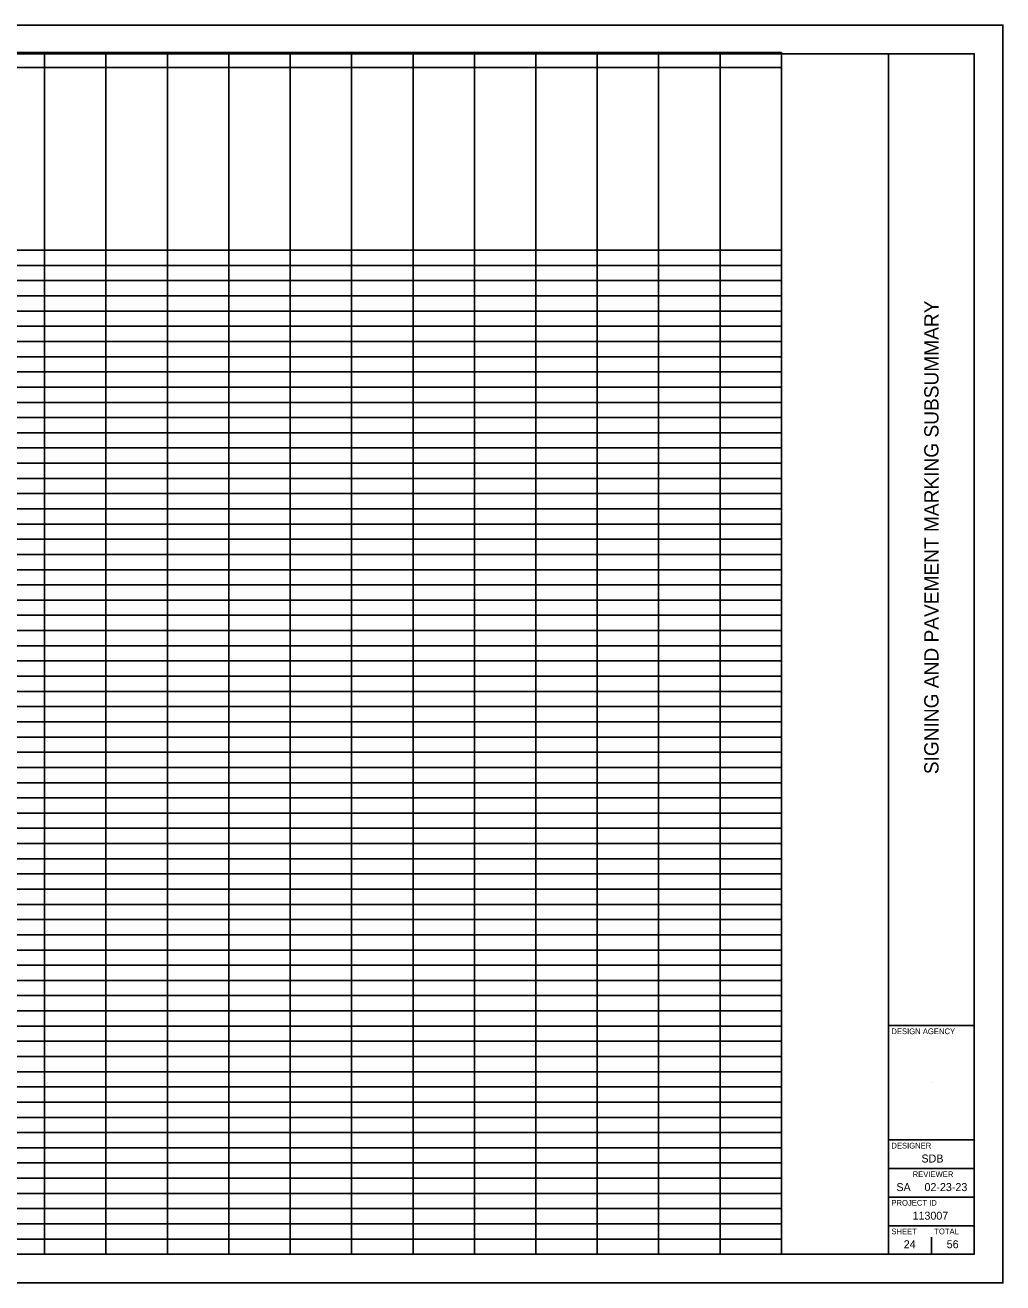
# Model space of a CAD drawing. Extents: x 0 to 34, y 0 to 22.
# Drawn here: x 16.9 to 34, y 0 to 22 of the extents above; entities that cross this region are included whole.
import ezdxf

# ---------------------------------------------------------------- set-up
doc = ezdxf.new("R2010")
doc.units = 0
for name, color, linetype in [('SH_Border', 7, 'Continuous'), ('SH_Cut_Line', 7, 'Continuous'), ('SH_Data', 7, 'Continuous'), ('SH_Text', 7, 'Continuous')]:
    doc.layers.add(name, color=color, linetype=linetype)

msp = doc.modelspace()

# ---------------------------------------------------------------- linework, layer by layer
at = {"layer": 'SH_Border'}
for p, q in [((32, 0.5), (32, 21.5)), ((32, 4.5), (33.5, 4.5)), ((32, 2.5), (33.5, 2.5)), ((32, 2), (33.5, 2)), ((32, 1.5), (33.5, 1.5)), ((32, 1), (33.5, 1))]:
    msp.add_line(p, q, dxfattribs=at)
msp.add_lwpolyline([(1.5, 21.5), (33.5, 21.5), (33.5, 0.5), (1.5, 0.5)], close=True, dxfattribs=at)
at = {"layer": 'SH_Cut_Line'}
msp.add_lwpolyline([(0, 0), (34, 0), (34, 22), (0, 22)], close=True, dxfattribs=at)
at = {"layer": 'SH_Data'}
for p, q in [((32.75, 3.5), (32.75, 3.5)), ((32.375, 0.675), (32.375, 0.675)), ((32.75, 0.5), (32.75, 0.8))]:
    msp.add_line(p, q, dxfattribs=at)
at = {"layer": 'SH_Text'}
for p, q in [((1.5, 21.523), (30.127, 21.523)), ((17.235, 21.523), (17.235, 0.5)), ((18.309, 21.523), (18.309, 0.5)), ((19.384, 21.523), (19.384, 0.5)), ((20.458, 21.523), (20.458, 0.5)), ((21.532, 21.523), (21.532, 0.5)), ((22.607, 21.523), (22.607, 0.5)), ((23.681, 21.523), (23.681, 0.5)), ((24.755, 21.523), (24.755, 0.5)), ((25.83, 21.523), (25.83, 0.5)), ((26.904, 21.523), (26.904, 0.5)), ((27.978, 21.523), (27.978, 0.5)), ((29.052, 21.523), (29.052, 0.5)), ((30.127, 21.523), (30.127, 0.5)), ((9.715, 21.257), (30.127, 21.257)), ((9.715, 18.063), (30.127, 18.063)), ((1.5, 17.797), (30.127, 17.797)), ((1.5, 17.531), (30.127, 17.531)), ((1.5, 17.265), (30.127, 17.265)), ((1.5, 16.999), (30.127, 16.999)), ((1.5, 16.733), (30.127, 16.733)), ((1.5, 16.467), (30.127, 16.467)), ((1.5, 16.201), (30.127, 16.201)), ((1.5, 15.935), (30.127, 15.935)), ((1.5, 15.668), (30.127, 15.668)), ((1.5, 15.402), (30.127, 15.402)), ((1.5, 15.136), (30.127, 15.136)), ((1.5, 14.87), (30.127, 14.87)), ((1.5, 14.604), (30.127, 14.604)), ((1.5, 14.338), (30.127, 14.338)), ((1.5, 14.072), (30.127, 14.072)), ((1.5, 13.806), (30.127, 13.806)), ((1.5, 13.539), (30.127, 13.539)), ((1.5, 13.273), (30.127, 13.273)), ((1.5, 13.007), (30.127, 13.007)), ((1.5, 12.741), (30.127, 12.741)), ((1.5, 12.475), (30.127, 12.475)), ((1.5, 12.209), (30.127, 12.209)), ((1.5, 11.943), (30.127, 11.943)), ((1.5, 11.677), (30.127, 11.677)), ((1.5, 11.411), (30.127, 11.411)), ((1.5, 11.144), (30.127, 11.144)), ((1.5, 10.878), (30.127, 10.878)), ((1.5, 10.612), (30.127, 10.612)), ((1.5, 10.346), (30.127, 10.346)), ((1.5, 10.08), (30.127, 10.08)), ((1.5, 9.814), (30.127, 9.814)), ((1.5, 9.548), (30.127, 9.548)), ((1.5, 9.282), (30.127, 9.282)), ((1.5, 9.016), (30.127, 9.016)), ((1.5, 8.749), (30.127, 8.749)), ((1.5, 8.483), (30.127, 8.483)), ((1.5, 8.217), (30.127, 8.217)), ((1.5, 7.951), (30.127, 7.951)), ((1.5, 7.685), (30.127, 7.685)), ((1.5, 7.419), (30.127, 7.419)), ((1.5, 7.153), (30.127, 7.153)), ((1.5, 6.887), (30.127, 6.887)), ((1.5, 6.621), (30.127, 6.621)), ((1.5, 6.354), (30.127, 6.354)), ((1.5, 6.088), (30.127, 6.088)), ((1.5, 5.822), (30.127, 5.822)), ((1.5, 5.556), (30.127, 5.556)), ((1.5, 5.29), (30.127, 5.29)), ((1.5, 5.024), (30.127, 5.024)), ((1.5, 4.758), (30.127, 4.758)), ((1.5, 4.492), (30.127, 4.492)), ((1.5, 4.226), (30.127, 4.226)), ((1.5, 3.959), (30.127, 3.959)), ((1.5, 3.693), (30.127, 3.693)), ((1.5, 3.427), (30.127, 3.427)), ((1.5, 3.161), (30.127, 3.161)), ((1.5, 2.895), (30.127, 2.895)), ((1.5, 2.629), (30.127, 2.629)), ((1.5, 2.363), (30.127, 2.363)), ((1.5, 2.097), (30.127, 2.097)), ((1.5, 1.831), (30.127, 1.831)), ((1.5, 1.564), (30.127, 1.564)), ((1.5, 1.298), (30.127, 1.298)), ((1.5, 1.032), (30.127, 1.032)), ((8.641, 0.766), (30.127, 0.766)), ((1.5, 0.5), (30.127, 0.5))]:
    msp.add_line(p, q, dxfattribs=at)

# ---------------------------------------------------------------- texts
at = {"layer": 'SH_Data'}
msp.add_text('SIGNING AND PAVEMENT MARKING SUBSUMMARY', height=0.25, rotation=90, dxfattribs=at).set_placement((32.875, 8.898))
for s, height, p in [('DESIGN AGENCY', 0.1, (32.05, 4.35)), ('DESIGNER', 0.1, (32.05, 2.35)), ('SDB', 0.14, (32.576, 2.105)), ('REVIEWER', 0.1, (32.422, 1.85)), ('SA', 0.14, (32.138, 1.605)), ('02-23-23', 0.14, (32.629, 1.605)), ('PROJECT ID', 0.1, (32.05, 1.35)), ('113007', 0.14, (32.42, 1.105)), ('SHEET', 0.1, (32.05, 0.85)), ('TOTAL', 0.1, (32.8, 0.85)), ('24', 0.14, (32.266, 0.605)), ('56', 0.14, (33.018, 0.605))]:
    msp.add_text(s, height=height, dxfattribs=at).set_placement(p)

doc.saveas('drawing.dxf')
